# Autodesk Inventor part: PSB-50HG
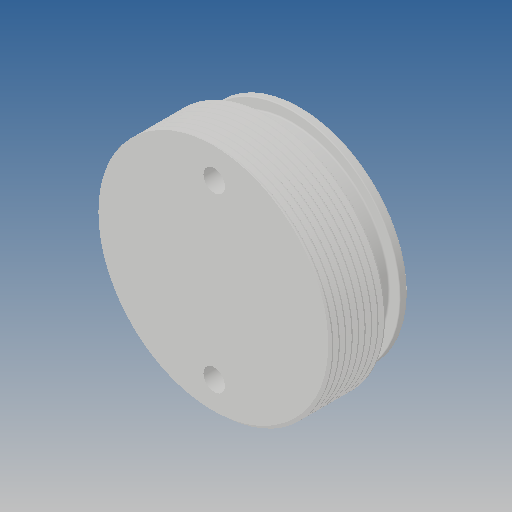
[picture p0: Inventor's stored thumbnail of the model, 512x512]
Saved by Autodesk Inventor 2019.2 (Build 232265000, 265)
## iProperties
Created: 2010-02
Part Number: PSB-50HG
Material: Ogólny
Document SubType Name: Modeling
Designer: CADENGINEERING4
Density: 1 g/cm^3
Appearance: Domyślna
Author: CADENGINEERING4
Revision Number: 1LAST_VERSION
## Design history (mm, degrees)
feature "Baza1"
node "Bryła1"
